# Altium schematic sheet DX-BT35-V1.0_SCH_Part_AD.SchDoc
size A4
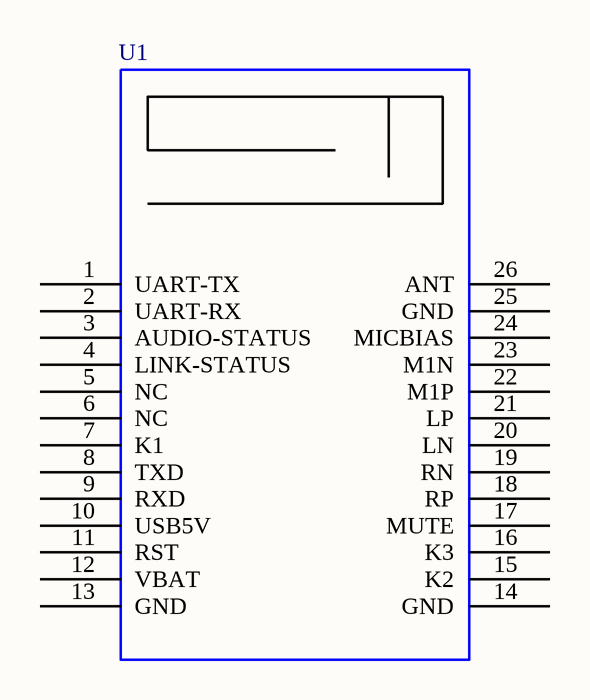
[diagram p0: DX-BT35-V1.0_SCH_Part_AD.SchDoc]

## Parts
U1  Component_1  (value not drawn)

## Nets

Not connected (* = marked no-connect by the designer): U1 1(UART-TX) 2(UART-RX) 3(AUDIO-STATUS) 4(LINK-STATUS) 5(NC) 6(NC) 7(K1) 8(TXD) 9(RXD) 10(USB5V) 11(RST) 12(VBAT) 13(GND) 14(GND) 15(K2) 16(K3) 17(MUTE) 18(RP) 19(RN) 20(LN) 21(LP) 22(M1P) 23(M1N) 24(MICBIAS) 25(GND) 26(ANT)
